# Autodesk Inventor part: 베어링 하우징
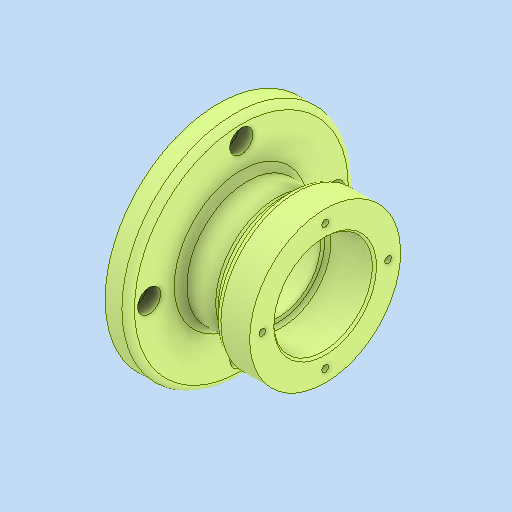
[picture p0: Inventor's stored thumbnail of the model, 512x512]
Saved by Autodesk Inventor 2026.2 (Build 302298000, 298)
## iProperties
Created: 2026-01
Part Number: 베어링 하우징
Material: 알루미늄 6061
Document SubType Name: Modeling
Designer: PC2-07
Density: 2.7 g/cm^3
Appearance: 기본값
Author: jhkim
Sending System: Autodesk Inventor 2026
Preprocessor: ST-DEVELOPER v20.1
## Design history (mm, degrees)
feature "솔리드1"
node "솔리드2"
